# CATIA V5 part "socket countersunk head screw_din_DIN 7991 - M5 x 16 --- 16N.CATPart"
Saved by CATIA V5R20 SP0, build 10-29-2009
Part number: socket countersunk head screw_din_DIN 7991 - M5 x 16 --- 16N
Revision: ANY
Definition: UNKNOWN
Nomenclature: socket countersunk head screw_din_DIN 7991 - M5 x 16 --- 16N
Source: Unknown
Bounding box of the stored display mesh (mm): x 0 to 16, y -4.82 to 4.82, z -4.82 to 4.82
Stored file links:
  C:\Users\Utente\Desktop\IO LAVORO\3D X SITO CF\CUMSA\3D files GR\GR 182622-15\socket countersunk head screw_din_DIN 7991 - M5 x 16 --- 16N.CATPart
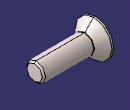
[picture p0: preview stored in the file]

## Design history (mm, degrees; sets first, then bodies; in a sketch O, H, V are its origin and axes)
Body1 "Hex" (main body)
  Solid1: solid without history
